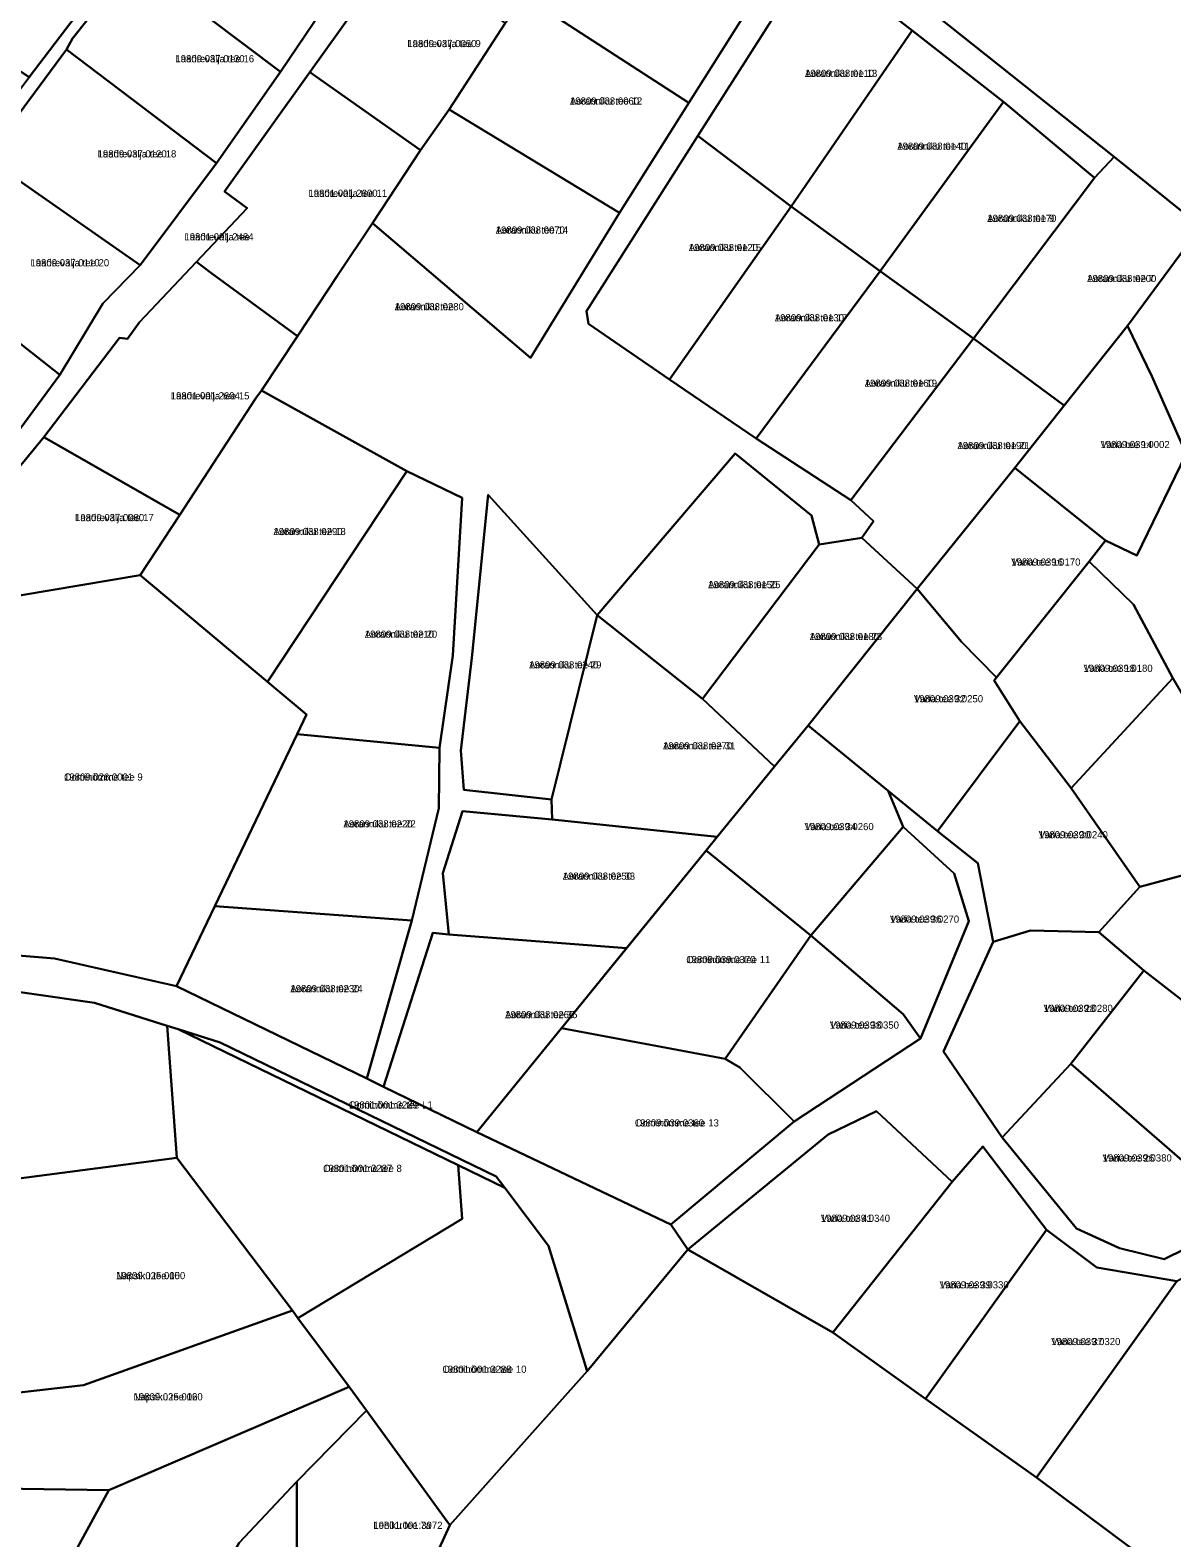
# Model space of a CAD drawing. Extents: x 516875 to 535633, y 6574491 to 6593094.
# Drawn here: x 521215.5 to 521454.9, y 6587635.9 to 6587952 of the extents above; entities that cross this region are included whole.
import ezdxf

# ---------------------------------------------------------------- set-up
doc = ezdxf.new("R2010")
doc.units = 0
for name, color, linetype in [('L_AADRESS', 7, 'Continuous'), ('PIIR', 7, 'Continuous'), ('TUNNUS', 7, 'Continuous')]:
    doc.layers.add(name, color=color, linetype=linetype)

msp = doc.modelspace()

# ---------------------------------------------------------------- linework, layer by layer
at = {"layer": 'PIIR'}
for points in [[(521456.62, 6588003.29), (521471.41, 6588015.99), (521485.51, 6588006.06), (521484.65, 6588005.35), (521514.67, 6587973.91), (521492.26, 6587947.79), (521477.81, 6587930.85), (521464.56, 6587914.78), (521461.03, 6587910.82), (521442.87, 6587925.41), (521402.67, 6587957.39), (521436.92, 6587986.49)], [(521200.27, 6587987.77), (521231.42, 6587963.35), (521215.28, 6587942.14), (521181.69, 6587964.04)], [(521251.54, 6587984.76), (521281.97, 6587963.99), (521267.98, 6587943.22), (521237.28, 6587966.42)], [(521368.68, 6587960.59), (521353.63, 6587936.77), (521319.16, 6587959.1), (521334.13, 6587981.66), (521334.68, 6587982.43)], [(521292.9, 6587969.35), (521315.09, 6587953.45), (521303.38, 6587935.38), (521297.34, 6587926.82), (521274.13, 6587943.17)], [(521224.36, 6587950.23), (521237.28, 6587966.42), (521267.98, 6587943.22), (521254.61, 6587924.08), (521223.14, 6587947.9)], [(521400.47, 6587951.9), (521375.09, 6587915), (521355.54, 6587929.86), (521379.8, 6587967.93)], [(521353.63, 6587936.77), (521339.07, 6587913.66), (521303.38, 6587935.38), (521315.09, 6587953.45), (521319.16, 6587959.1)], [(521419.63, 6587936.99), (521393.75, 6587901.49), (521375.09, 6587915), (521400.47, 6587951.9)], [(521223.14, 6587947.9), (521254.61, 6587924.08), (521238.55, 6587902.7), (521206.25, 6587925.23)], [(521256.28, 6587918.15), (521274.13, 6587943.17), (521297.34, 6587926.82), (521287.33, 6587911.5), (521279.93, 6587900.52), (521271.6, 6587887.81), (521253.36, 6587901.19), (521250.4, 6587903.41), (521261.05, 6587914.65)], [(521339.07, 6587913.66), (521320.46, 6587883.28), (521287.33, 6587911.5), (521297.34, 6587926.82), (521303.38, 6587935.38)], [(521438.72, 6587921.03), (521413.33, 6587887.37), (521393.75, 6587901.49), (521419.63, 6587936.99)], [(521375.09, 6587915), (521349.61, 6587878.74), (521332.58, 6587890.41), (521332.19, 6587893.07), (521355.54, 6587929.86)], [(521206.25, 6587925.23), (521238.55, 6587902.7), (521230.76, 6587894.66), (521221.72, 6587879.71), (521190.37, 6587904.4)], [(521461.03, 6587910.82), (521445.64, 6587890.03), (521432.36, 6587873.27), (521413.33, 6587887.37), (521438.72, 6587921.03), (521442.87, 6587925.41)], [(521393.75, 6587901.49), (521367.73, 6587866.41), (521349.61, 6587878.74), (521375.09, 6587915)], [(521464.56, 6587914.78), (521484.84, 6587893.28), (521488.81, 6587886.04), (521495.27, 6587879.8), (521476.69, 6587878.48), (521457.92, 6587863.19), (521450.71, 6587879.46), (521445.64, 6587890.03), (521461.03, 6587910.82)], [(521190.37, 6587904.4), (521221.72, 6587879.71), (521208.57, 6587861.94), (521174.85, 6587884.73)], [(521218.38, 6587866.68), (521234.27, 6587887.51), (521235.92, 6587887.25), (521238.44, 6587890.79), (521250.4, 6587903.41), (521253.36, 6587901.19), (521271.6, 6587887.81), (521263.99, 6587876.45), (521262.86, 6587874.86), (521246.87, 6587850.38)], [(521413.33, 6587887.37), (521387.6, 6587853.44), (521367.73, 6587866.41), (521393.75, 6587901.49)], [(521432.36, 6587873.27), (521422.04, 6587860.25), (521401.52, 6587834.89), (521389.94, 6587845.52), (521392.37, 6587849.04), (521387.6, 6587853.44), (521413.33, 6587887.37)], [(521432.36, 6587873.27), (521445.64, 6587890.03), (521450.71, 6587879.46), (521457.92, 6587863.19), (521447.59, 6587841.85), (521441.02, 6587845.01), (521422.04, 6587860.25)], [(521294.49, 6587859.51), (521265.31, 6587815.39), (521238.56, 6587837.74), (521246.87, 6587850.38), (521262.86, 6587874.86), (521263.99, 6587876.45)], [(521198.47, 6587833.76), (521196.13, 6587839.69), (521218.38, 6587866.68), (521246.87, 6587850.38), (521238.56, 6587837.74), (521201.18, 6587831.42)], [(521379.4, 6587850.23), (521380.98, 6587844.19), (521356.5, 6587811.78), (521334.42, 6587829.33), (521363.33, 6587863.23)], [(521306.09, 6587853.92), (521304.15, 6587820.86), (521301.37, 6587801.5), (521271.52, 6587804.36), (521273.46, 6587808.53), (521265.31, 6587815.39), (521294.49, 6587859.51)], [(521410.83, 6587823.78), (521401.52, 6587834.89), (521422.04, 6587860.25), (521441.02, 6587845.01), (521437.6, 6587840.58), (521418.15, 6587816.26)], [(521334.42, 6587829.33), (521324.86, 6587790.7), (521306.46, 6587792.71), (521305.86, 6587800.97), (521308.11, 6587820.39), (521311.57, 6587854.6)], [(521401.52, 6587834.89), (521378.66, 6587806.21), (521371.61, 6587797.58), (521356.5, 6587811.78), (521380.98, 6587844.19), (521389.94, 6587845.52)], [(521423.05, 6587807.15), (521417.7, 6587815.67), (521418.15, 6587816.26), (521437.6, 6587840.58), (521446.92, 6587831.55), (521455.11, 6587816.12), (521433.82, 6587793.04)], [(521184.43, 6587828.89), (521186.73, 6587829.22), (521194.54, 6587830.65), (521198.47, 6587833.76), (521201.18, 6587831.42), (521238.56, 6587837.74), (521265.31, 6587815.39), (521273.46, 6587808.53), (521271.52, 6587804.36), (521254.25, 6587768.36), (521246.23, 6587751.58), (521220.58, 6587757.39), (521188.36, 6587760.02), (521177.71, 6587760.53), (521170.1, 6587760.17), (521172.33, 6587764.08), (521177.03, 6587787.15)], [(521378.66, 6587806.21), (521401.52, 6587834.89), (521410.83, 6587823.78), (521418.15, 6587816.26), (521417.7, 6587815.67), (521423.05, 6587807.15), (521405.81, 6587784.06), (521395.42, 6587792.49)], [(521356.5, 6587811.78), (521371.61, 6587797.58), (521359.59, 6587782.87), (521325, 6587786.47), (521324.86, 6587790.7), (521334.42, 6587829.33)], [(521433.82, 6587793.04), (521455.11, 6587816.12), (521476.24, 6587779.96), (521448.22, 6587772.4)], [(521359.59, 6587782.87), (521371.61, 6587797.58), (521378.66, 6587806.21), (521395.42, 6587792.49), (521398.57, 6587784.97), (521379.26, 6587762.16), (521357.26, 6587780.02)], [(521414.22, 6587777.32), (521405.81, 6587784.06), (521423.05, 6587807.15), (521433.82, 6587793.04), (521448.22, 6587772.4), (521439.66, 6587762.86), (521425.29, 6587763.2), (521417.46, 6587760.83)], [(521301.37, 6587801.5), (521301.2, 6587788.85), (521295.55, 6587765.32), (521254.25, 6587768.36), (521271.52, 6587804.36)], [(521325, 6587786.47), (521359.59, 6587782.87), (521357.26, 6587780.02), (521340.59, 6587759.5), (521303.31, 6587762.4), (521302.02, 6587775.24), (521306.19, 6587788.25)], [(521398.57, 6587784.97), (521409.3, 6587775.19), (521412.39, 6587765.2), (521402.21, 6587740.62), (521398.57, 6587745.66), (521379.26, 6587762.16)], [(521357.26, 6587780.02), (521379.26, 6587762.16), (521361.27, 6587736.34), (521326.97, 6587742.73)], [(521449.07, 6587754.87), (521439.66, 6587762.86), (521448.22, 6587772.4), (521476.24, 6587779.96), (521481.67, 6587766.22), (521482.89, 6587750.45), (521469.93, 6587747.02), (521465.88, 6587741.81)], [(521295.55, 6587765.32), (521295.02, 6587763.4), (521286.09, 6587732.23), (521246.23, 6587751.58), (521254.25, 6587768.36)], [(521303.31, 6587762.4), (521340.59, 6587759.5), (521326.97, 6587742.73), (521309.2, 6587720.98), (521289.62, 6587730.47), (521299.93, 6587762.77)], [(521364.36, 6587734.53), (521361.27, 6587736.34), (521379.26, 6587762.16), (521398.57, 6587745.66), (521402.21, 6587740.62), (521375.71, 6587723.16)], [(521407.02, 6587737.87), (521417.46, 6587760.83), (521425.29, 6587763.2), (521439.66, 6587762.86), (521449.07, 6587754.87), (521433.72, 6587735.31), (521419.37, 6587719.87)], [(521449.07, 6587754.87), (521465.88, 6587741.81), (521469.93, 6587747.02), (521482.89, 6587750.45), (521477.72, 6587731.74), (521464.52, 6587708.57), (521433.72, 6587735.31)], [(521158.75, 6587697.02), (521147.49, 6587694.6), (521129.39, 6587753.93), (521188.07, 6587753.93), (521228.98, 6587748.06), (521244.21, 6587743.28), (521246.3, 6587715.54), (521203.94, 6587710.02), (521183.95, 6587707.43)], [(521246.3, 6587715.54), (521244.21, 6587743.28), (521246.54, 6587742.54), (521305.29, 6587714.02), (521306.08, 6587702.75), (521271.62, 6587681.93), (521270.51, 6587683.54)], [(521305.29, 6587714.02), (521246.54, 6587742.54), (521255.35, 6587739.77), (521313.26, 6587711.63), (521315.04, 6587709.28)], [(521326.97, 6587742.73), (521361.27, 6587736.34), (521364.36, 6587734.53), (521375.71, 6587723.16), (521349.87, 6587701.57), (521309.2, 6587720.98)], [(521419.37, 6587719.87), (521433.72, 6587735.31), (521464.52, 6587708.57), (521457.72, 6587696.53), (521453.35, 6587694.3), (521443.95, 6587696.65), (521434.91, 6587700.79)], [(521382.85, 6587720.48), (521393.03, 6587725.36), (521408.84, 6587710.55), (521383.82, 6587678.95), (521353.41, 6587696.37)], [(521383.82, 6587678.95), (521408.84, 6587710.55), (521415.33, 6587717.95), (521428.62, 6587700.46), (521403.29, 6587665.06)], [(521198.46, 6587664.72), (521203.94, 6587710.02), (521246.3, 6587715.54), (521270.51, 6587683.54), (521226.68, 6587667.93)], [(521282.44, 6587667.57), (521271.62, 6587681.93), (521306.08, 6587702.75), (521305.29, 6587714.02), (521315.04, 6587709.28), (521324.23, 6587697.11), (521332.32, 6587670.88), (521303.54, 6587638.57), (521286.07, 6587662.57)], [(521403.29, 6587665.06), (521428.62, 6587700.46), (521439.19, 6587692.6), (521455.99, 6587689.7), (521426.52, 6587648.56)], [(521455.99, 6587689.7), (521462.55, 6587693.47), (521478.18, 6587693.28), (521490.98, 6587685.72), (521477.23, 6587667.12), (521469.89, 6587631.13), (521466.85, 6587618.54), (521426.52, 6587648.56)], [(521195.66, 6587646.45), (521198.46, 6587664.72), (521226.68, 6587667.93), (521270.51, 6587683.54), (521271.62, 6587681.93), (521282.44, 6587667.57), (521232.03, 6587645.92)], [(521228.67, 6587582.51), (521203.6, 6587594.02), (521206.82, 6587600), (521232.03, 6587645.92), (521282.44, 6587667.57), (521286.07, 6587662.57), (521271.42, 6587647.73), (521259.36, 6587634.86), (521229.89, 6587584.44)], [(521286.07, 6587662.57), (521303.54, 6587638.57), (521290.9, 6587610.86), (521271.45, 6587634.05), (521271.42, 6587647.73)], [(521244.47, 6587574.45), (521228.67, 6587582.51), (521229.89, 6587584.44), (521259.36, 6587634.86), (521271.42, 6587647.73), (521271.45, 6587634.05), (521290.9, 6587610.86), (521273.53, 6587582.85), (521258.87, 6587562.81)], [(521179.72, 6587611.08), (521182.41, 6587646.46), (521195.66, 6587646.45), (521232.03, 6587645.92), (521206.82, 6587600), (521203.6, 6587594.02), (521178.83, 6587595.76)]]:
    msp.add_lwpolyline(points, close=True, dxfattribs=at)
for points in [[(521292.9, 6587969.35), (521274.13, 6587943.17), (521256.28, 6587918.15), (521261.05, 6587914.65), (521238.44, 6587890.79), (521235.92, 6587887.25), (521234.27, 6587887.51), (521218.38, 6587866.68), (521196.13, 6587839.69)], [(521237.28, 6587966.42), (521224.36, 6587950.23), (521223.14, 6587947.9), (521206.25, 6587925.23), (521190.37, 6587904.4), (521174.85, 6587884.73), (521163.81, 6587870.86), (521162.35, 6587871.82), (521181.85, 6587896.84), (521197.1, 6587918.25), (521215.28, 6587942.14), (521231.42, 6587963.35)], [(521402.67, 6587957.39), (521442.87, 6587925.41), (521438.72, 6587921.03), (521419.63, 6587936.99), (521400.47, 6587951.9), (521379.8, 6587967.93), (521355.54, 6587929.86), (521332.19, 6587893.07), (521332.58, 6587890.41), (521349.61, 6587878.74), (521367.73, 6587866.41), (521387.6, 6587853.44), (521392.37, 6587849.04), (521389.94, 6587845.52), (521380.98, 6587844.19), (521379.4, 6587850.23), (521363.33, 6587863.23), (521334.42, 6587829.33), (521311.57, 6587854.6), (521308.11, 6587820.39), (521305.86, 6587800.97), (521306.46, 6587792.71), (521324.86, 6587790.7), (521325, 6587786.47), (521306.19, 6587788.25), (521302.02, 6587775.24), (521303.31, 6587762.4), (521299.93, 6587762.77), (521289.62, 6587730.47), (521286.09, 6587732.23), (521295.02, 6587763.4), (521295.55, 6587765.32), (521301.2, 6587788.85), (521301.37, 6587801.5), (521304.15, 6587820.86), (521306.09, 6587853.92), (521294.49, 6587859.51), (521263.99, 6587876.45), (521271.6, 6587887.81), (521279.93, 6587900.52), (521287.33, 6587911.5), (521320.46, 6587883.28), (521339.07, 6587913.66), (521353.63, 6587936.77), (521368.68, 6587960.59)], [(521208.57, 6587861.94), (521221.72, 6587879.71), (521230.76, 6587894.66), (521238.55, 6587902.7), (521254.61, 6587924.08), (521267.98, 6587943.22), (521281.97, 6587963.99)], [(521455.11, 6587816.12), (521446.92, 6587831.55), (521437.6, 6587840.58), (521441.02, 6587845.01), (521447.59, 6587841.85), (521457.92, 6587863.19)], [(521455.99, 6587689.7), (521439.19, 6587692.6), (521428.62, 6587700.46), (521415.33, 6587717.95), (521408.84, 6587710.55), (521393.03, 6587725.36), (521382.85, 6587720.48), (521353.41, 6587696.37), (521349.87, 6587701.57), (521375.71, 6587723.16), (521402.21, 6587740.62), (521412.39, 6587765.2), (521409.3, 6587775.19), (521398.57, 6587784.97), (521395.42, 6587792.49), (521405.81, 6587784.06), (521414.22, 6587777.32), (521417.46, 6587760.83), (521407.02, 6587737.87), (521419.37, 6587719.87), (521434.91, 6587700.79), (521443.95, 6587696.65), (521453.35, 6587694.3), (521457.72, 6587696.53)], [(521188.36, 6587760.02), (521220.58, 6587757.39), (521246.23, 6587751.58), (521286.09, 6587732.23), (521289.62, 6587730.47), (521309.2, 6587720.98), (521349.87, 6587701.57), (521353.41, 6587696.37), (521332.32, 6587670.88), (521324.23, 6587697.11), (521315.04, 6587709.28), (521313.26, 6587711.63), (521255.35, 6587739.77), (521246.54, 6587742.54), (521244.21, 6587743.28), (521228.98, 6587748.06), (521188.07, 6587753.93)], [(521321.81, 6587470.42), (521323.19, 6587480.09), (521321.45, 6587484.64), (521307.81, 6587497.68), (521267.05, 6587518.5), (521260.71, 6587524.03), (521258.87, 6587562.81), (521273.53, 6587582.85), (521290.9, 6587610.86), (521303.54, 6587638.57), (521332.32, 6587670.88), (521353.41, 6587696.37), (521383.82, 6587678.95), (521403.29, 6587665.06), (521426.52, 6587648.56), (521466.85, 6587618.54), (521494, 6587586.23), (521612.94, 6587444.85)]]:
    msp.add_lwpolyline(points, dxfattribs=at)

# ---------------------------------------------------------------- texts
at = {"layer": 'L_AADRESS'}
for s, p in [('Laadrevälja tee 9', (521294.61, 6587948.43)), ('Laadrevälja tee 16', (521245.97, 6587945.25)), ('Aoranniku tee 13', (521378, 6587942.18)), ('Aoranniku tee 12', (521328.71, 6587936.38)), ('Aoranniku tee 11', (521397.36, 6587926.91)), ('Laadrevälja tee 18', (521229.65, 6587925.3)), ('Laadrevälja tee 11', (521273.87, 6587917.04)), ('Aoranniku tee 9', (521416.23, 6587911.78)), ('Laadrevälja tee', (521247.86, 6587907.91)), ('Aoranniku tee 14', (521313.15, 6587909.33)), ('Aoranniku tee 15', (521353.64, 6587905.67)), ('Laadrevälja tee 20', (521215.57, 6587902.47)), ('Aoranniku tee 7', (521437.18, 6587899.17)), ('Aoranniku tee', (521291.96, 6587893.26)), ('Aoranniku tee 17', (521371.68, 6587890.94)), ('Aoranniku tee 19', (521390.53, 6587877.23)), ('Laadrevälja tee 15', (521244.99, 6587874.58)), ('Aoranniku tee 21', (521409.98, 6587864.15)), ('Varia tee 14', (521439.98, 6587864.37)), ('Laadrevälja tee 17', (521224.92, 6587849.05)), ('Aoranniku tee 18', (521266.53, 6587846.13)), ('Varia tee 16', (521421.27, 6587839.73)), ('Aoranniku tee 25', (521357.7, 6587835)), ('Aoranniku tee 20', (521285.7, 6587824.61)), ('Aoranniku tee 23', (521379.01, 6587824.12)), ('Aoranniku tee 29', (521320.14, 6587818.17)), ('Varia tee 18', (521436.41, 6587817.46)), ('Varia tee 32', (521400.85, 6587811.07)), ('Aoranniku tee 31', (521348.23, 6587801.2)), ('Oominõmme tee 9', (521222.61, 6587794.66)), ('Aoranniku tee 22', (521281.2, 6587784.84)), ('Varia tee 34', (521377.91, 6587784.27)), ('Varia tee 30', (521427.02, 6587782.56)), ('Aoranniku tee 33', (521327.21, 6587773.88)), ('Varia tee 36', (521395.82, 6587764.87)), ('Oominõmme tee 11', (521353.11, 6587756.39)), ('Aoranniku tee 24', (521270.07, 6587750.29)), ('Aoranniku tee 35', (521315.11, 6587744.85)), ('Varia tee 28', (521428.05, 6587746.17)), ('Varia tee 38', (521383.21, 6587742.66)), ('Oominõmme tee L1', (521282.33, 6587725.91)), ('Oominõmme tee 13', (521342.33, 6587722.15)), ('Oominõmme tee 8', (521276.95, 6587712.61)), ('Varia tee 26', (521440.42, 6587714.8)), ('Varia tee 41', (521381.33, 6587702.15)), ('Napsiku tee 10', (521233.53, 6587690.13)), ('Varia tee 39', (521406.22, 6587688.2)), ('Varia tee 37', (521429.64, 6587676.31)), ('Oominõmme tee 10', (521301.97, 6587670.5)), ('Napsiku tee 12', (521237.19, 6587664.73)), ('Lehiku tee 7a', (521287.48, 6587637.79))]:
    msp.add_text(s, height=1.5, dxfattribs=at).set_placement(p)
at = {"layer": 'TUNNUS'}
for s, p in [('19809:037:0050', (521294.61, 6587948.43)), ('19809:037:0130', (521245.97, 6587945.25)), ('19809:038:0110', (521378, 6587942.18)), ('19809:038:0060', (521328.71, 6587936.38)), ('19809:038:0140', (521397.36, 6587926.91)), ('19809:037:0120', (521229.65, 6587925.3)), ('19801:001:2600', (521273.87, 6587917.04)), ('19809:038:0170', (521416.23, 6587911.78)), ('19801:001:2484', (521247.86, 6587907.91)), ('19809:038:0070', (521313.15, 6587909.33)), ('19809:038:0120', (521353.64, 6587905.67)), ('19809:037:0110', (521215.57, 6587902.47)), ('19809:038:0200', (521437.18, 6587899.17)), ('19809:038:0280', (521291.96, 6587893.26)), ('19809:038:0130', (521371.68, 6587890.94)), ('19809:038:0160', (521390.53, 6587877.23)), ('19801:001:2604', (521244.99, 6587874.58)), ('19809:038:0190', (521409.98, 6587864.15)), ('19809:039:0002', (521439.98, 6587864.37)), ('19809:037:0080', (521224.92, 6587849.05)), ('19809:038:0290', (521266.53, 6587846.13)), ('19809:039:0170', (521421.27, 6587839.73)), ('19809:038:0150', (521357.7, 6587835)), ('19809:038:0210', (521285.7, 6587824.61)), ('19809:038:0180', (521379.01, 6587824.12)), ('19809:038:0240', (521320.14, 6587818.17)), ('19809:039:0180', (521436.41, 6587817.46)), ('19809:039:0250', (521400.85, 6587811.07)), ('19809:038:0270', (521348.23, 6587801.2)), ('19809:026:0001', (521222.61, 6587794.66)), ('19809:038:0220', (521281.2, 6587784.84)), ('19809:039:0260', (521377.91, 6587784.27)), ('19809:039:0240', (521427.02, 6587782.56)), ('19809:038:0250', (521327.21, 6587773.88)), ('19809:039:0270', (521395.82, 6587764.87)), ('19809:039:0370', (521353.11, 6587756.39)), ('19809:038:0230', (521270.07, 6587750.29)), ('19809:038:0260', (521315.11, 6587744.85)), ('19809:039:0280', (521428.05, 6587746.17)), ('19809:039:0350', (521383.21, 6587742.66)), ('19801:001:3289', (521282.33, 6587725.91)), ('19809:039:0360', (521342.33, 6587722.15)), ('19801:001:3287', (521276.95, 6587712.61)), ('19809:039:0380', (521440.42, 6587714.8)), ('19809:039:0340', (521381.33, 6587702.15)), ('19809:025:0050', (521233.53, 6587690.13)), ('19809:039:0330', (521406.22, 6587688.2)), ('19809:039:0320', (521429.64, 6587676.31)), ('19801:001:3288', (521301.97, 6587670.5)), ('19809:025:0060', (521237.19, 6587664.73)), ('19801:001:3972', (521287.48, 6587637.79))]:
    msp.add_text(s, height=1.5, dxfattribs=at).set_placement(p)

doc.saveas('drawing.dxf')
